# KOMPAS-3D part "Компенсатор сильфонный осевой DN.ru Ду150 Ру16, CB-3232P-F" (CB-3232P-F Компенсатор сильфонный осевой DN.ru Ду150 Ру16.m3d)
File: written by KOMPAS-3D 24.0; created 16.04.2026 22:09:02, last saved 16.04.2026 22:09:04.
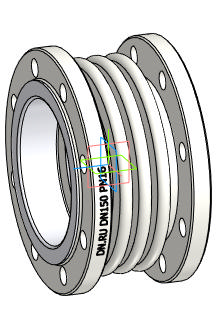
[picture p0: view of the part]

Document properties: Автор: DN.RU; Полное имя файла: D:\PROJECT CAD\DN.RU\..199(ACTUALE). CB-3232P-F Компенсатор сильфонный осевой DN.ru\Исходники\DN150\CB-3232P-F Компенсатор сильфонный осевой DN.ru Ду150 Ру16.m3d

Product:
- Body: Твердое тело1  | qty 1
    Масса: 18.79873
- Part/product: Компенсатор сильфонный осевой DN.ru Ду150 Ру16  | designation CB-3232P-F
    Масса: 15.2
    Раздел спецификации: Прочие изделия
    Комментарий: D140-02143
    Примечание: D140-02143
    additional columns: Типовые

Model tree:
1. Твердое тело1  (labels: Твердое тело1)

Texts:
  CB-3232P-F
